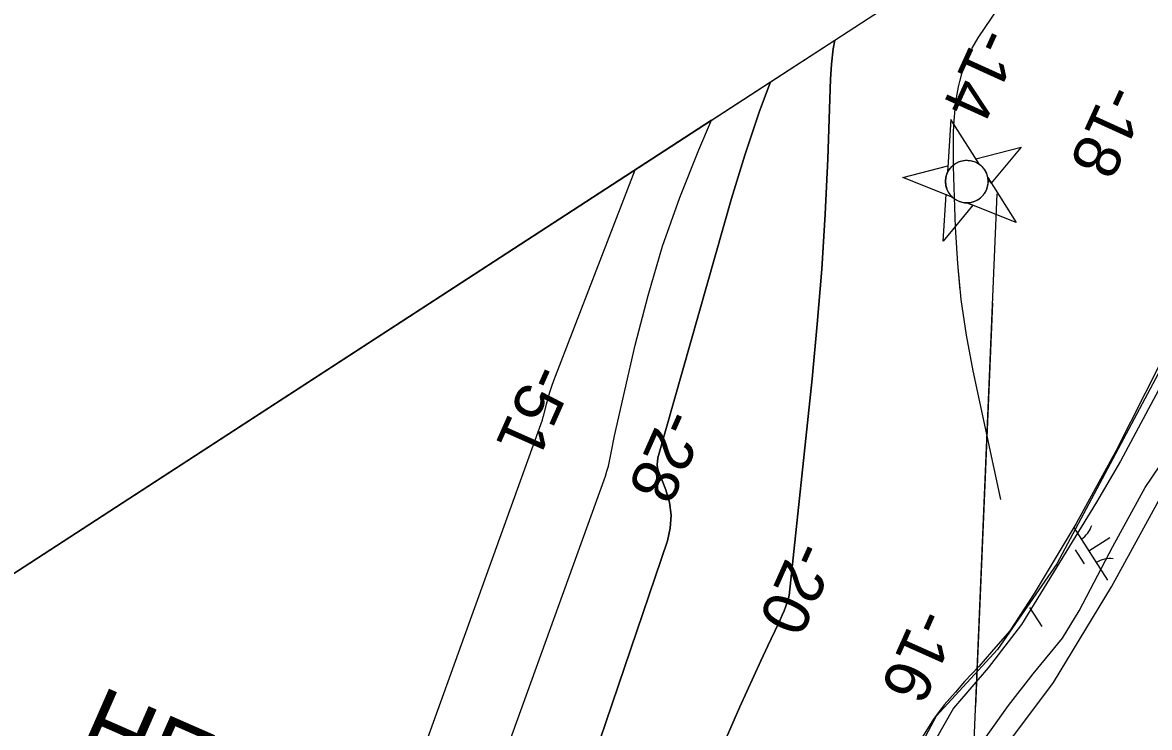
# Model space of a CAD drawing. Extents: x 3937982 to 3958556, y 219448 to 241894.
# Drawn here: x 3943113 to 3943922, y 235576 to 236082 of the extents above; entities that cross this region are included whole.
import ezdxf

# ---------------------------------------------------------------- set-up
doc = ezdxf.new("R2010")
doc.units = 0
for name, color, linetype in [('V-CHAN-NAID', 7, 'Continuous'), ('V-GRID-FRAM', 7, 'Continuous'), ('V-RIVR-EDGE', 7, 'Continuous'), ('V-RIVR-JETY', 7, 'Continuous'), ('V-RIVR-RANG', 7, 'Continuous'), ('V-RRAP-FSHR', 7, 'Continuous'), ('V-TOPO-DPTH', 7, 'Continuous'), ('V-TOPO-MAJR', 7, 'Continuous'), ('V-TOPO-MINR', 7, 'Continuous'), ('V-WETL-SWMP', 7, 'Continuous')]:
    doc.layers.add(name, color=color, linetype=linetype)

msp = doc.modelspace()

# ---------------------------------------------------------------- linework, layer by layer
at = {"layer": 'V-CHAN-NAID'}
for points in [[(3943799.979, 235979.919), (3943779.535, 236012.243), (3943777.076, 235974.075), (3943777.578, 235975.059), (3943778.044, 235975.84), (3943778.649, 235976.719), (3943779.325, 235977.567), (3943779.783, 235978.078), (3943780.369, 235978.669), (3943780.911, 235979.162), (3943781.532, 235979.673), (3943782.233, 235980.188), (3943782.895, 235980.62), (3943783.796, 235981.136), (3943784.527, 235981.496), (3943785.559, 235981.927), (3943786.498, 235982.244), (3943787.455, 235982.5), (3943788.338, 235982.679), (3943789.203, 235982.802), (3943790.068, 235982.874), (3943791.086, 235982.897), (3943791.983, 235982.861), (3943792.787, 235982.783), (3943793.54, 235982.671), (3943794.456, 235982.482), (3943795.146, 235982.301), (3943796.198, 235981.956), (3943796.891, 235981.681), (3943797.797, 235981.261), (3943798.663, 235980.788), (3943799.341, 235980.365)], [(3943799.979, 235979.919), (3943797.417, 235983.97), (3943829.832, 235992.24), (3943808.469, 235966.496), (3943805.906, 235970.548), (3943805.723, 235971.367), (3943805.418, 235972.416), (3943805.056, 235973.396), (3943804.636, 235974.336), (3943804.368, 235974.858), (3943803.988, 235975.525), (3943803.522, 235976.249), (3943803.122, 235976.806), (3943802.522, 235977.554), (3943802.061, 235978.069), (3943801.417, 235978.716), (3943800.827, 235979.246), (3943800.409, 235979.59)], [(3943780.509, 235956.455), (3943744.969, 235970.589), (3943777.384, 235978.859), (3943777.076, 235974.075), (3943776.842, 235973.547), (3943776.433, 235972.463), (3943776.166, 235971.57), (3943775.93, 235970.547), (3943775.779, 235969.625), (3943775.685, 235968.701), (3943775.649, 235967.844), (3943775.667, 235966.858), (3943775.747, 235965.891), (3943775.89, 235964.918), (3943776.047, 235964.16), (3943776.264, 235963.332), (3943776.628, 235962.243), (3943776.922, 235961.521), (3943777.361, 235960.6), (3943777.733, 235959.925), (3943778.226, 235959.136), (3943778.716, 235958.447), (3943779.252, 235957.775), (3943779.897, 235957.059)], [(3943805.906, 235970.548), (3943826.35, 235938.223), (3943790.811, 235952.358), (3943791.683, 235952.377), (3943792.725, 235952.465), (3943793.585, 235952.592), (3943794.607, 235952.81), (3943795.505, 235953.063), (3943796.302, 235953.338), (3943797.245, 235953.73), (3943797.957, 235954.077), (3943798.919, 235954.621), (3943799.778, 235955.19), (3943800.661, 235955.87), (3943801.329, 235956.457), (3943802.135, 235957.266), (3943802.862, 235958.114), (3943803.493, 235958.965), (3943803.925, 235959.628), (3943804.459, 235960.569), (3943804.896, 235961.481), (3943805.284, 235962.452), (3943805.591, 235963.398), (3943805.822, 235964.302), (3943806.025, 235965.403), (3943806.148, 235966.518), (3943806.188, 235967.544), (3943806.155, 235968.644), (3943806.077, 235969.469)], [(3943790.811, 235952.358), (3943795.265, 235950.586), (3943773.902, 235924.843), (3943776.054, 235958.227), (3943780.509, 235956.455), (3943781.159, 235955.883), (3943781.83, 235955.356), (3943782.798, 235954.695), (3943783.639, 235954.204), (3943784.612, 235953.72), (3943785.592, 235953.316), (3943786.535, 235953), (3943787.374, 235952.774), (3943788.345, 235952.576), (3943789.26, 235952.448), (3943790.182, 235952.375)]]:
    msp.add_lwpolyline(points, close=True, dxfattribs=at)
msp.add_circle((3943790.918, 235967.628), 15.27, dxfattribs=at)
at = {"layer": 'V-GRID-FRAM'}
msp.add_lwpolyline([(3948998.173, 239513.74), (3957109.469, 226912.286), (3949780.097, 222173.81), (3941699.799, 234772.334), (3948998.173, 239513.74)], dxfattribs=at)
at = {"layer": 'V-RIVR-EDGE'}
msp.add_lwpolyline([(3944193.63, 236392.457), (3944193.155, 236391.169), (3944172.689, 236343.94), (3944119.949, 236234.524), (3944097.121, 236194.379), (3944079.017, 236141.639), (3944066.422, 236128.257), (3944040.446, 236067.646), (3944007.385, 235995.227), (3943991.642, 235945.636), (3943960.942, 235890.535), (3943855.463, 235692.957), (3943812.956, 235631.558), (3943768.875, 235583.541), (3943727.155, 235505.612), (3943670.48, 235374.156), (3943636.632, 235260.018), (3943585.466, 235124.626), (3943579.956, 235075.035), (3943597.274, 234983.724), (3943619.314, 234871.947)], dxfattribs=at)
at = {"layer": 'V-RIVR-JETY'}
for points in [[(3943928.492, 235817.704), (3943901.241, 235766.865), (3943884.044, 235737.39), (3943862.071, 235701.333), (3943830.114, 235649.385), (3943806.253, 235618.436), (3943781.247, 235589.453), (3943762.434, 235556.091), (3943739.648, 235517.701), (3943721.195, 235481.988), (3943702.208, 235435.338), (3943681.935, 235380.11), (3943659.284, 235322.565), (3943636.093, 235253.695)], [(3943667.822, 235259.137), (3943681.648, 235299.601), (3943698.266, 235344.327), (3943716.092, 235391.773), (3943732.244, 235431.034), (3943747.932, 235464.436), (3943760.783, 235490.452), (3943776.817, 235520.726), (3943797.244, 235557.975), (3943820.744, 235591.275), (3943838.636, 235614.096), (3943859.687, 235639.612), (3943871.674, 235659.388), (3943895.738, 235705.576), (3943918.966, 235747.869), (3943940.493, 235779.634)]]:
    msp.add_lwpolyline(points, dxfattribs=at)
at = {"layer": 'V-RIVR-RANG'}
for points in [[(3943812.557, 235958.749), (3943771.737, 234990.891)], [(3943812.557, 235958.749), (3943771.737, 234990.891)], [(3943809.252, 235880.387), (3943797.032, 235590.645)]]:
    msp.add_lwpolyline(points, dxfattribs=at)
at = {"layer": 'V-RRAP-FSHR'}
msp.add_lwpolyline([(3943648.444, 234864.923), (3943633.272, 234943.444), (3943617.876, 235021.948), (3943622.994, 235100.327), (3943650.171, 235175.566), (3943678.906, 235250.224), (3943708.387, 235324.593), (3943738.82, 235398.878), (3943769.606, 235472.399), (3943805.37, 235543.862), (3943853.205, 235607.915), (3943894.849, 235676.646), (3943933.18, 235746.524), (3943970.3, 235817.305), (3944005.82, 235888.983), (3944041.119, 235960.773), (3944076.417, 236032.566), (3944110.874, 236104.758), (3944144.447, 236177.374), (3944176.138, 236250.819), (3944207.167, 236324.555), (3944236.607, 236398.941), (3944248.265, 236427.951)], dxfattribs=at)
at = {"layer": 'V-TOPO-DPTH'}
for p, q in [((3943649.988, 236039.279), (3943696.147, 236069.266)), ((3943607.545, 236011.706), (3943649.988, 236039.279)), ((3943607.545, 236011.706), (3942326.909, 235179.738))]:
    msp.add_line(p, q, dxfattribs=at)
for points in [[(3943696.147, 236069.266), (3943695.051, 236062.942), (3943693.854, 236052.029), (3943693.109, 236041.053), (3943691.02, 235983.895), (3943689.163, 235944.321), (3943686.759, 235904.786), (3943683.536, 235865.309), (3943679.767, 235825.871), (3943663.28, 235670.425), (3943663.169, 235669.564), (3943663.088, 235669.227), (3943663.037, 235669.062), (3943660.838, 235662.711), (3943659.627, 235659.394), (3943658.342, 235656.108), (3943656.946, 235652.867), (3943655.477, 235649.656), (3943648.095, 235634.217), (3943642.936, 235623.284), (3943637.853, 235612.316), (3943632.883, 235601.296), (3943627.989, 235590.242), (3943479.736, 235250.682)], [(3943216.56, 234819.199), (3943359.149, 235134.282), (3943401.325, 235231.27), (3943441.563, 235329.023), (3943478.894, 235427.922), (3943514.288, 235527.585), (3943575.911, 235709.589), (3943577.945, 235718.793), (3943578.669, 235727.961), (3943577.426, 235737.072), (3943574.872, 235746.146), (3943569.473, 235759.537), (3943568.789, 235761.899), (3943568.423, 235764.278), (3943568.967, 235769.103), (3943622.026, 235955.368), (3943631.55, 235986.579), (3943641.839, 236017.519), (3943649.988, 236039.279)], [(3943649.988, 236039.279), (3943641.839, 236017.519), (3943631.55, 235986.579), (3943622.026, 235955.368), (3943568.967, 235769.103), (3943568.423, 235764.278), (3943568.789, 235761.899), (3943569.473, 235759.537), (3943574.872, 235746.146), (3943577.426, 235737.072), (3943578.669, 235727.961), (3943577.945, 235718.793), (3943575.911, 235709.589), (3943514.288, 235527.585), (3943478.894, 235427.922), (3943441.563, 235329.023), (3943401.325, 235231.27), (3943359.149, 235134.282), (3943216.56, 234819.199)], [(3943179.881, 234824.293), (3943232.683, 234950.164), (3943259.501, 235015.481), (3943285.653, 235081.057), (3943310.805, 235147.024), (3943335.29, 235213.251), (3943531.312, 235756.093), (3943532.475, 235759.609), (3943533.509, 235763.158), (3943534.349, 235766.759), (3943535.06, 235770.393), (3943535.705, 235774.047), (3943536.392, 235777.692), (3943537.143, 235781.324), (3943537.936, 235784.949), (3943552.762, 235850.011), (3943561.959, 235885.849), (3943572.427, 235921.273), (3943584.8, 235956.077), (3943598.444, 235990.468), (3943607.545, 236011.706)], [(3943179.881, 234824.293), (3943232.683, 234950.164), (3943259.501, 235015.481), (3943285.653, 235081.057), (3943310.805, 235147.024), (3943335.29, 235213.251), (3943531.312, 235756.093), (3943532.475, 235759.609), (3943533.509, 235763.158), (3943534.349, 235766.759), (3943535.06, 235770.393), (3943535.705, 235774.047), (3943536.392, 235777.692), (3943537.143, 235781.324), (3943537.936, 235784.949), (3943552.762, 235850.011), (3943561.959, 235885.849), (3943572.427, 235921.273), (3943584.8, 235956.077), (3943598.444, 235990.468), (3943607.545, 236011.706)]]:
    msp.add_lwpolyline(points, dxfattribs=at)
at = {"layer": 'V-TOPO-MAJR'}
msp.add_lwpolyline([(3943160.398, 234892.777), (3943486.229, 235796.554), (3943486.748, 235798.602), (3943486.927, 235799.431), (3943487.026, 235799.843), (3943489.006, 235807.732), (3943490.178, 235812.063), (3943491.453, 235816.361), (3943492.885, 235820.609), (3943494.421, 235824.825), (3943552.669, 235976.056)], dxfattribs=at)
at = {"layer": 'V-TOPO-MINR'}
for points in [[(3943815.27, 235739.24), (3943795.455, 235831.641), (3943790.678, 235857.248), (3943786.822, 235882.969), (3943784.347, 235908.858), (3943782.794, 235934.861), (3943781.616, 235970.705), (3943781.411, 235978.872), (3943781.291, 235987.039), (3943781.299, 235995.208), (3943781.392, 236003.377), (3943781.777, 236011.521), (3943782.463, 236019.63), (3943783.602, 236027.689), (3943785.043, 236035.714), (3943785.841, 236039.544), (3943788.089, 236047.841), (3943790.949, 236055.879), (3943794.729, 236063.527), (3943799.121, 236070.916), (3943876.733, 236185.534), (3943877.982, 236187.396)], [(3943794.648, 236063.365), (3943794.729, 236063.527), (3943799.121, 236070.916), (3943876.733, 236185.534), (3943877.982, 236187.396)], [(3943479.736, 235250.682), (3943627.989, 235590.242), (3943632.883, 235601.296), (3943637.853, 235612.316), (3943642.936, 235623.284), (3943648.095, 235634.217), (3943655.477, 235649.656), (3943656.946, 235652.867), (3943658.342, 235656.108), (3943659.627, 235659.394), (3943660.838, 235662.711), (3943663.037, 235669.062), (3943663.088, 235669.227), (3943663.169, 235669.564), (3943663.28, 235670.425), (3943679.767, 235825.871), (3943683.536, 235865.309), (3943686.759, 235904.786), (3943689.163, 235944.321), (3943691.02, 235983.895), (3943693.109, 236041.053), (3943693.854, 236052.029), (3943695.051, 236062.942), (3943696.147, 236069.266)], [(3943216.56, 234819.199), (3943359.149, 235134.282), (3943401.325, 235231.27), (3943441.563, 235329.023), (3943478.894, 235427.922), (3943514.288, 235527.585), (3943575.911, 235709.589), (3943577.945, 235718.793), (3943578.669, 235727.961), (3943577.426, 235737.072), (3943574.872, 235746.146), (3943569.473, 235759.537), (3943568.789, 235761.899), (3943568.423, 235764.278), (3943568.967, 235769.103), (3943622.026, 235955.368), (3943631.55, 235986.579), (3943641.839, 236017.519), (3943649.988, 236039.279)], [(3943179.881, 234824.293), (3943232.683, 234950.164), (3943259.501, 235015.481), (3943285.653, 235081.057), (3943310.805, 235147.024), (3943335.29, 235213.251), (3943531.312, 235756.093), (3943532.475, 235759.609), (3943533.509, 235763.158), (3943534.349, 235766.759), (3943535.06, 235770.393), (3943535.705, 235774.047), (3943536.392, 235777.692), (3943537.143, 235781.324), (3943537.936, 235784.949), (3943552.762, 235850.011), (3943561.959, 235885.849), (3943572.427, 235921.273), (3943584.8, 235956.077), (3943598.444, 235990.468), (3943607.545, 236011.706)], [(3943786.18, 235889.68), (3943784.347, 235908.858), (3943782.794, 235934.861), (3943781.616, 235970.705), (3943781.411, 235978.872), (3943781.291, 235987.039), (3943781.295, 235990.85)], [(3943812.557, 235958.749), (3943771.737, 234990.891)]]:
    msp.add_lwpolyline(points, dxfattribs=at)
at = {"layer": 'V-WETL-SWMP'}
for p, q in [((3943962.314, 235901.421), (3943897.877, 235774.016)), ((3943897.877, 235774.016), (3943869.547, 235722.147)), ((3943869.547, 235722.147), (3943839.301, 235671.687)), ((3943867.696, 235719.059), (3943891.986, 235681.322)), ((3943878.455, 235702.344), (3943893.59, 235712.086)), ((3943868.72, 235703.213), (3943875.214, 235693.123)), ((3943839.301, 235671.687), (3943821.806, 235644.829)), ((3943836.037, 235661.607), (3943844.697, 235648.153)), ((3943821.806, 235644.829), (3943808.615, 235629.801)), ((3943808.615, 235629.801), (3943799.632, 235619.416)), ((3943799.632, 235619.416), (3943789.259, 235608.497)), ((3943789.259, 235608.497), (3943782.8, 235600.843)), ((3943782.8, 235600.843), (3943774.665, 235591.829)), ((3943774.665, 235591.829), (3943767.063, 235581.425)), ((3943767.063, 235581.425), (3943751.253, 235556.481))]:
    msp.add_line(p, q, dxfattribs=at)
for centre, start, end in [((3943863.704, 235725.698), 301.99668, 343.540338), ((3943893.604, 235679.247), 81.996677, 123.540335)]:
    msp.add_arc(centre, 17.623, start, end, dxfattribs=at)

# ---------------------------------------------------------------- texts
at = {"layer": 'V-CHAN-NAID'}
msp.add_text('HEAD RANGE', height=50, rotation=336.30966, dxfattribs=at).set_placement((3943149.715, 235559.799))
at = {"layer": 'V-RIVR-RANG'}
for s, rotation, p in [('-14', 245.548326, (3943799.807, 236080.562)), ('-18', 245.548326, (3943891.104, 236039.755)), ('-51', 246.041, (3943478.578, 235838.969)), ('-28', 246.041, (3943573.578, 235806.514)), ('-20', 245.898326, (3943667.38, 235711.82)), ('-16', 245.898326, (3943755.155, 235663.146))]:
    msp.add_text(s, height=33.5, rotation=rotation, dxfattribs=at).set_placement(p)

doc.saveas('drawing.dxf')
